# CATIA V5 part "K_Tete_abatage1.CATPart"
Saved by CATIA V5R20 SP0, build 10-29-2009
Part number: Tete_abatage1
Bounding box of the stored display mesh (mm): x -15 to 15, y 180.997 to 250.957, z 22.748 to 92.911
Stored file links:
  G:\Khaled_CFAO_2011\ST2M\ST2M_GR1\hgrenier\Khaled\CAD_ThinkMOTION\K_Tete_abatage1.CATPart
  C:\Users\Tom\Documents\Cours 2A\CFAO\Projet thinkmotion\Hugo\porte_outil.CATProduct
  G:\Khaled_CFAO_2011\ST2M\ST2M_GR1\hgrenier\Khaled\CAD_ThinkMOTION\K_Squelette.CATPart
  G:\Khaled_CFAO_2011\ST2M\ST2M_GR1\hgrenier\Khaled\CAD_ThinkMOTION\K_Bielette2.CATPart
  G:\Khaled_CFAO_2011\ST2M\ST2M_GR1\hgrenier\Khaled\CAD_ThinkMOTION\K_Tete_abatage2.CATPart
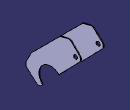
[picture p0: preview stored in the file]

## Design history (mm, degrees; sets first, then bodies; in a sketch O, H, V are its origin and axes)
External parameters (linked from other documents)
  External.Rayon = 2.5697 mm
Set1
  Plane1 "Plan_bielle2": linked copy from another document
  Plane2 "plan_sym": linked copy from another document
  Point1 "Centre_bielette2/tête": linked copy from another document
  DatumSurface1: linked copy from another document
Body1 (main body)
  Sketch1 on Plane1, origin (15, 0, 0), H (0, 1, 0), V (0, 0, 1)
    line L1 (238.1636, 92.369) -> (253.0329, 77.8643)
    line L2 (253.0329, 77.8643) -> (238.5046, 62.9707)
    arc A1 centre (212.7262, 36.5444) radius 15 from (223.2004, 47.2818) to (202.2521, 25.8069) ccw
    point P4 (212.7262, 36.5444)
    line L3 (238.5046, 62.9707) -> (223.2004, 47.2818)
    line L4 (238.1636, 92.369) -> (235.0903, 92.9114)
    line L5 (235.0903, 92.9114) -> (224.6181, 90.2282)
    line L6 (224.6181, 90.2282) -> (188.1484, 53.813)
    line L7 (188.1484, 53.813) -> (180.9966, 40.333)
    line L8 (180.9966, 40.333) -> (181.3798, 35.4776)
    line L9 (181.3798, 35.4776) -> (197.3451, 20.7766)
    point P11 (197.3451, 20.7766)
    line L10 (197.3451, 20.7766) -> (202.2521, 25.8069)
    radius A1 = 15
    perpendicularity: L2 L1
    coincidence: P4 L2, P11 L2
    parallelism: L3 L2, L10 L2
  Pad1: profile Sketch1, direction (-1, 0, 0), length 1
  Fillet1: radius 5, on edge [face of Pad1 from Sketch1.L9 | face of Pad1 from Sketch1.L10]; edge [face of Pad1 from Sketch1.L2 | face of Pad1 from Sketch1.L1]
  Sketch2 on start face of Pad1, origin (15, 0, 0), H (0, 1, 0), V (0, 0, 1)
    circle A1 centre (244.422, 77.441) radius 2.5697
    point P1 (244.422, 77.441)
    reference projected point E1 (244.422, 77.441) from Point1
    radius A1 = 2.5697 {= External.Rayon}
    coincidence: P1 E1
  Pocket1: profile Sketch2, direction (-1, 0, 0), length 1
  Mirror1: of the body so far, about Plane2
